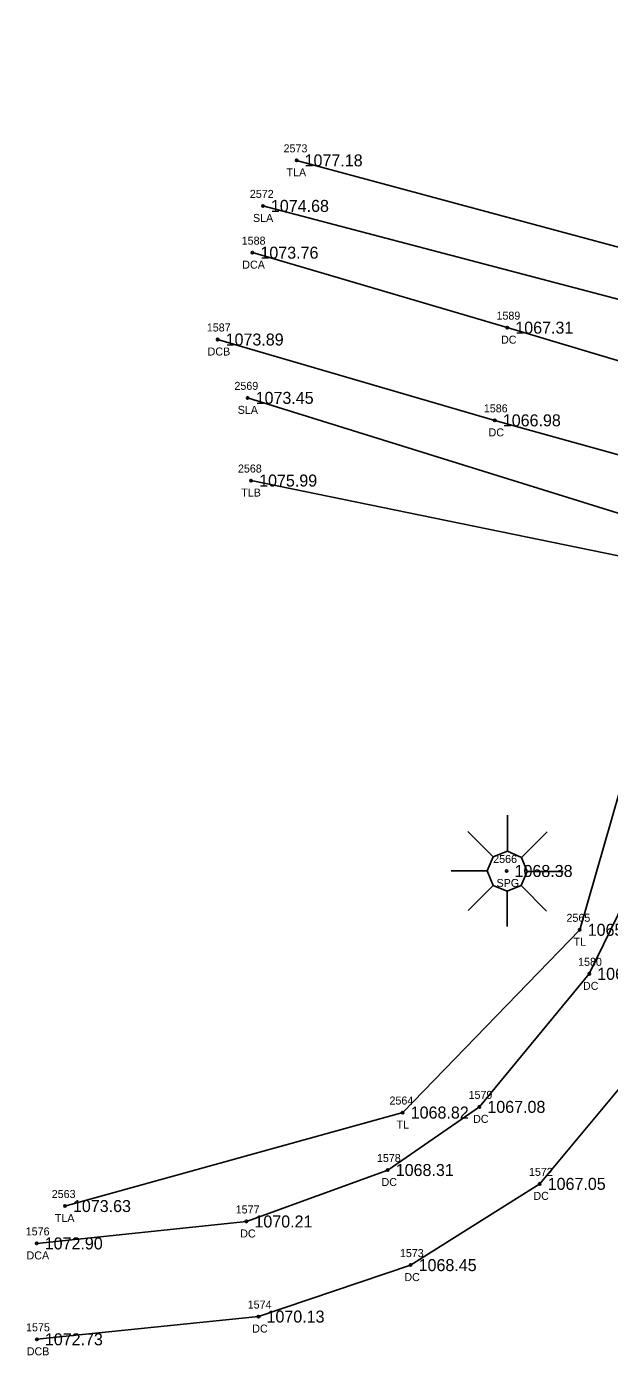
# Model space of a CAD drawing. Extents: x 1578957 to 1581675, y 1115963 to 1120391.
# Drawn here: x 1580388.2 to 1580461, y 1118522.1 to 1118688.1 of the extents above; entities that cross this region are included whole.
import ezdxf

# ---------------------------------------------------------------- set-up
doc = ezdxf.new("R2010")
doc.units = 0
for name, color, linetype in [('RD_EX_BldgApp', 7, 'Continuous'), ('RD_EX_BldgApp_txCode', 7, 'Continuous'), ('RD_EX_Conc', 7, 'Continuous'), ('RD_EX_Conc_txCode', 7, 'Continuous'), ('RD_EX_TX_BldgApp_ELEV', 7, 'Continuous'), ('RD_EX_TX_Conc_ELEV', 7, 'Continuous'), ('RD_EX_TX_VEG_ELEV', 7, 'Continuous'), ('RD_EX_VEG', 7, 'Continuous'), ('RD_EX_VEG_txCode', 7, 'Continuous'), ('RD_SMD_Locator', 7, 'Continuous')]:
    doc.layers.add(name, color=color, linetype=linetype)

msp = doc.modelspace()

# ---------------------------------------------------------------- linework, layer by layer
at = {"layer": 'RD_EX_BldgApp'}
for p, q in [((1580448.27, 1118585.05), (1580448.27, 1118589.56)), ((1580446.48, 1118584.35), (1580443.3, 1118587.53)), ((1580450.02, 1118584.28), (1580453.22, 1118587.47)), ((1580445.74, 1118582.58), (1580441.22, 1118582.58)), ((1580450.74, 1118582.5), (1580455.24, 1118582.5)), ((1580446.46, 1118580.77), (1580443.34, 1118577.65)), ((1580449.97, 1118580.75), (1580453.16, 1118577.56)), ((1580448.23, 1118580.04), (1580448.23, 1118575.63))]:
    msp.add_line(p, q, dxfattribs=at)
msp.add_lwpolyline([(1580446.48, 1118584.35), (1580448.27, 1118585.05), (1580450.02, 1118584.28), (1580450.74, 1118582.5), (1580449.97, 1118580.75), (1580448.23, 1118580.04), (1580446.46, 1118580.77), (1580445.74, 1118582.58)], close=True, dxfattribs=at)
at = {"layer": 'RD_EX_Conc'}
for points in [[(1580416.39, 1118659.83), (1580448.24, 1118650.46), (1580491.67, 1118637.48)], [(1580389.43, 1118536.05), (1580415.64, 1118538.79), (1580433.3, 1118545.22), (1580444.75, 1118553.11), (1580458.48, 1118569.73), (1580464.72, 1118582.5), (1580474.92, 1118607.53), (1580480.39, 1118628.36), (1580466.62, 1118633.33), (1580446.68, 1118638.88), (1580412.04, 1118648.98)], [(1580492.21, 1118614.13), (1580485.46, 1118601.65), (1580476.91, 1118579.82), (1580466.27, 1118560.22), (1580452.29, 1118543.49), (1580436.16, 1118533.34), (1580417.15, 1118526.91), (1580389.45, 1118524.07)]]:
    msp.add_lwpolyline(points, dxfattribs=at)
at = {"layer": 'RD_EX_VEG'}
msp.add_line((1580417.7, 1118665.67), (1580477.41, 1118650.01), dxfattribs=at)
for points in [[(1580421.91, 1118671.36), (1580485.62, 1118654.18), (1580489.68, 1118707.91), (1580496.87, 1118741.57), (1580494.2, 1118750.41), (1580484.59, 1118756.1), (1580440.4, 1118760.4)], [(1580415.79, 1118641.69), (1580471.49, 1118624.35), (1580474.39, 1118620.17)], [(1580392.96, 1118540.72), (1580435.17, 1118552.4), (1580457.29, 1118575.23), (1580470.26, 1118620.3), (1580416.23, 1118631.36)]]:
    msp.add_lwpolyline(points, dxfattribs=at)
at = {"layer": 'RD_SMD_Locator'}
for centre in [(1580421.91, 1118671.36), (1580417.7, 1118665.67), (1580416.39, 1118659.83), (1580448.24, 1118650.46), (1580412.04, 1118648.98), (1580415.79, 1118641.69), (1580446.68, 1118638.88), (1580416.23, 1118631.36), (1580448.15, 1118582.58), (1580457.29, 1118575.23), (1580458.48, 1118569.73), (1580435.17, 1118552.4), (1580444.75, 1118553.11), (1580433.3, 1118545.22), (1580452.29, 1118543.49), (1580392.96, 1118540.72), (1580415.64, 1118538.79), (1580389.43, 1118536.05), (1580436.16, 1118533.34), (1580417.15, 1118526.91), (1580389.45, 1118524.07)]:
    msp.add_circle(centre, 0.15, dxfattribs=at)

# ---------------------------------------------------------------- texts
at = {"layer": 'RD_EX_BldgApp_txCode'}
for s, p in [('2566', (1580446.48, 1118583.58)), ('SPG', (1580446.9, 1118580.58))]:
    msp.add_text(s, height=1, dxfattribs=at).set_placement(p)
at = {"layer": 'RD_EX_Conc_txCode'}
for s, p in [('1588', (1580415.05, 1118660.83)), ('DCA', (1580415.12, 1118657.83)), ('1589', (1580446.89, 1118651.46)), ('1587', (1580410.69, 1118649.98)), ('DC', (1580447.46, 1118648.46)), ('DCB', (1580410.79, 1118646.98)), ('1586', (1580445.31, 1118639.88)), ('DC', (1580445.9, 1118636.88)), ('1580', (1580457.09, 1118570.73)), ('DC', (1580457.7, 1118567.73)), ('1579', (1580443.4, 1118554.11)), ('DC', (1580443.97, 1118551.11)), ('1578', (1580431.95, 1118546.22)), ('DC', (1580432.52, 1118543.22)), ('1572', (1580450.95, 1118544.49)), ('DC', (1580451.51, 1118541.49)), ('1577', (1580414.3, 1118539.79)), ('1576', (1580388.06, 1118537.05)), ('DC', (1580414.86, 1118536.79)), ('DCA', (1580388.16, 1118534.05)), ('1573', (1580434.82, 1118534.34)), ('DC', (1580435.38, 1118531.34)), ('1574', (1580415.8, 1118527.91)), ('1575', (1580388.1, 1118525.07)), ('DC', (1580416.37, 1118524.91)), ('DCB', (1580388.19, 1118522.07))]:
    msp.add_text(s, height=1, dxfattribs=at).set_placement(p)
at = {"layer": 'RD_EX_TX_BldgApp_ELEV'}
msp.add_text('1068.38', height=1.5, dxfattribs=at).set_placement((1580449.15, 1118581.83))
at = {"layer": 'RD_EX_TX_Conc_ELEV'}
for s, p in [('1073.76', (1580417.39, 1118659.08)), ('1067.31', (1580449.24, 1118649.71)), ('1073.89', (1580413.04, 1118648.23)), ('1066.98', (1580447.68, 1118638.13)), ('1065.02', (1580459.48, 1118568.98)), ('1067.08', (1580445.75, 1118552.36)), ('1068.31', (1580434.3, 1118544.47)), ('1067.05', (1580453.29, 1118542.74)), ('1070.21', (1580416.64, 1118538.04)), ('1072.90', (1580390.43, 1118535.3)), ('1068.45', (1580437.16, 1118532.59)), ('1070.13', (1580418.15, 1118526.16)), ('1072.73', (1580390.45, 1118523.32))]:
    msp.add_text(s, height=1.5, dxfattribs=at).set_placement(p)
at = {"layer": 'RD_EX_TX_VEG_ELEV'}
for s, p in [('1077.18', (1580422.91, 1118670.61)), ('1074.68', (1580418.7, 1118664.92)), ('1073.45', (1580416.79, 1118640.94)), ('1075.99', (1580417.23, 1118630.61)), ('1065.44', (1580458.29, 1118574.48)), ('1068.82', (1580436.17, 1118551.65)), ('1073.63', (1580393.96, 1118539.97))]:
    msp.add_text(s, height=1.5, dxfattribs=at).set_placement(p)
at = {"layer": 'RD_EX_VEG_txCode'}
for s, p in [('2573', (1580420.28, 1118672.36)), ('TLA', (1580420.65, 1118669.36)), ('2572', (1580416.07, 1118666.67)), ('SLA', (1580416.46, 1118663.67)), ('2569', (1580414.14, 1118642.69)), ('SLA', (1580414.55, 1118639.69)), ('2568', (1580414.58, 1118632.36)), ('TLB', (1580414.99, 1118629.36)), ('2565', (1580455.64, 1118576.23)), ('TL', (1580456.52, 1118573.23)), ('2564', (1580433.52, 1118553.4)), ('TL', (1580434.4, 1118550.4)), ('2563', (1580391.31, 1118541.72)), ('TLA', (1580391.7, 1118538.72))]:
    msp.add_text(s, height=1, dxfattribs=at).set_placement(p)

doc.saveas('drawing.dxf')
